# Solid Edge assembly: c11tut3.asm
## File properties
Author: CADCIM
Template: iso assembly.asm
Last saved by: CADCIM
Revision: 18
Application: Solid Edge
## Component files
Casting.par
Brasses.par
cap.par
Bolt.par
Nut.par
Lock Nut.par
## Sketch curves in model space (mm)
line (-97.5, -28, 0) -> (-97.5, -28, 2)
line (-97.5, -28, 2) -> (97.5, -28, 2)
line (97.5, -28, 2) -> (97.5, -28, 0)
line (97.5, -28, 0) -> (0, -28, 0)
line (0, -28, 0) -> (-97.5, -28, 0)
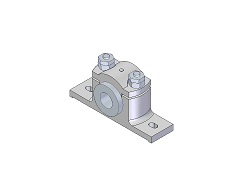
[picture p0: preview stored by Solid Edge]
